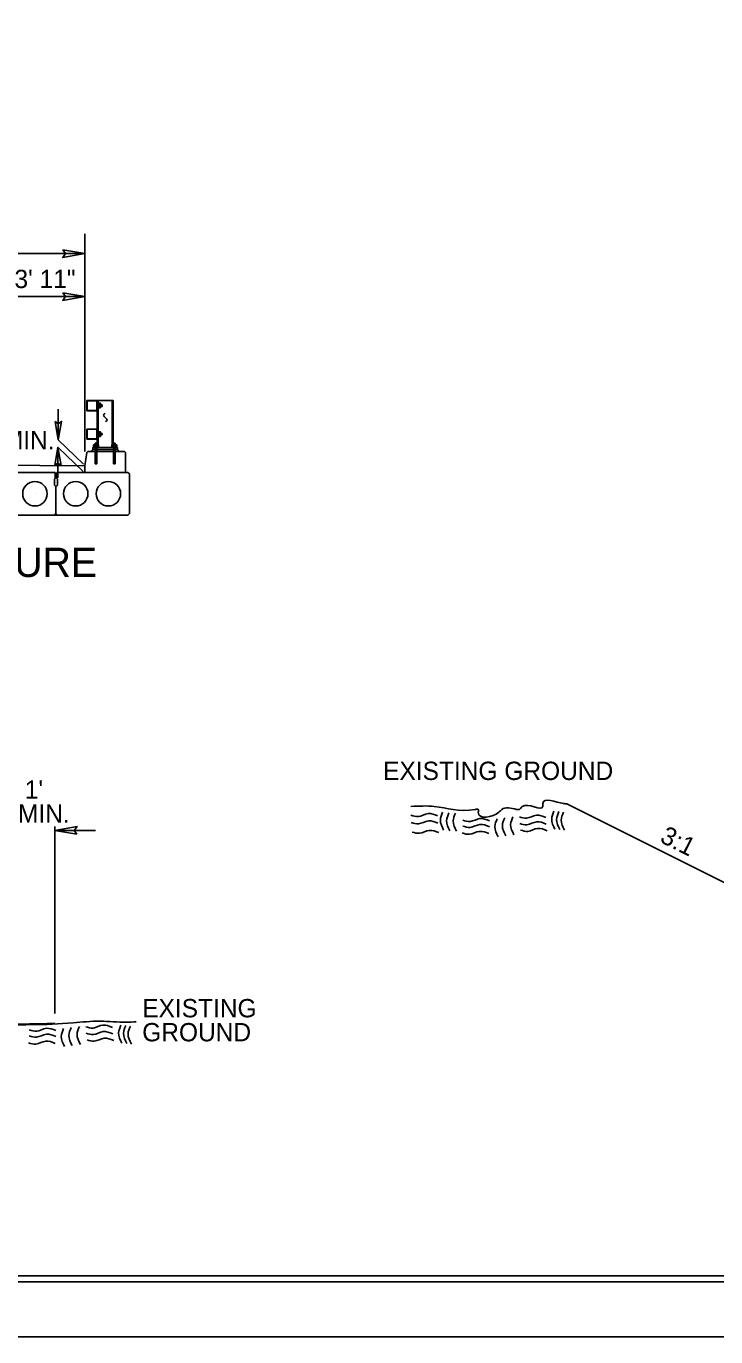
# Model space of a CAD drawing. Extents: x 575722 to 576066, y -53107 to -52774.
# Drawn here: x 575850.6 to 575878.8, y -53106.9 to -53053.2 of the extents above; entities that cross this region are included whole.
import ezdxf

# ---------------------------------------------------------------- set-up
doc = ezdxf.new("R2010")
doc.units = 0
for name, color, linetype in [('Default', 7, 'Continuous'), ('Old_Level_11', 7, 'Continuous'), ('Old_Level_2', 7, 'Continuous'), ('Prop Dimension', 7, 'Continuous'), ('Prop Dimension Text', 7, 'Continuous'), ('Prop DSN Text', 7, 'Continuous'), ('Sheet Cutting Line CELL', 7, 'Continuous'), ('Sheet Plot Border Inside CELL', 7, 'Continuous'), ('Sheet Plot Border Outside CELL', 7, 'Continuous'), ('Sheet Typical CELL', 7, 'Continuous'), ('Typical Slope Point Local CELL', 7, 'Continuous'), ('Typical Terminator CELL', 7, 'Continuous'), ('Typical Text Grade Point CELL', 7, 'Continuous')]:
    doc.layers.add(name, color=color, linetype=linetype)

msp = doc.modelspace()

# ---------------------------------------------------------------- linework, layer by layer
at = {"layer": 'Default'}
for p, q in [((575853.09, -53068.945), (575853.09, -53068.528)), ((575853.09, -53068.528), (575853.507, -53068.528)), ((575853.1, -53068.538), (575853.497, -53068.538)), ((575853.1, -53068.935), (575853.1, -53068.538)), ((575853.497, -53068.935), (575853.497, -53068.538)), ((575853.507, -53070.342), (575853.507, -53068.528)), ((575853.507, -53068.528), (575854.175, -53068.528)), ((575853.507, -53068.945), (575853.507, -53068.528)), ((575853.549, -53070.342), (575853.549, -53068.528)), ((575854.133, -53070.342), (575854.133, -53068.528)), ((575854.175, -53070.342), (575854.175, -53068.528)), ((575853.09, -53068.945), (575853.507, -53068.945)), ((575853.1, -53068.935), (575853.497, -53068.935)), ((575853.549, -53068.643), (575853.655, -53068.643)), ((575853.549, -53068.705), (575853.716, -53068.705)), ((575853.549, -53068.768), (575853.716, -53068.768)), ((575853.549, -53068.831), (575853.655, -53068.831)), ((575853.655, -53068.831), (575853.655, -53068.643)), ((575853.661, -53068.768), (575853.659, -53068.705)), ((575853.671, -53068.768), (575853.669, -53068.705)), ((575853.682, -53068.768), (575853.679, -53068.705)), ((575853.692, -53068.768), (575853.689, -53068.705)), ((575853.702, -53068.768), (575853.699, -53068.705)), ((575853.716, -53068.768), (575853.716, -53068.705)), ((575853.833, -53069.053), (575853.807, -53069.072)), ((575853.803, -53069.189), (575853.894, -53069.276)), ((575853.888, -53069.378), (575853.856, -53069.405)), ((575853.09, -53070.114), (575853.09, -53069.697)), ((575853.09, -53069.697), (575853.507, -53069.697)), ((575853.09, -53070.114), (575853.507, -53070.114)), ((575853.1, -53069.707), (575853.497, -53069.707)), ((575853.1, -53070.103), (575853.1, -53069.707)), ((575853.1, -53070.103), (575853.497, -53070.103)), ((575853.497, -53070.103), (575853.497, -53069.707)), ((575853.507, -53070.114), (575853.507, -53069.697)), ((575853.549, -53069.811), (575853.655, -53069.811)), ((575853.549, -53069.874), (575853.716, -53069.874)), ((575853.549, -53069.937), (575853.716, -53069.937)), ((575853.549, -53069.999), (575853.655, -53069.999)), ((575853.655, -53069.999), (575853.655, -53069.811)), ((575853.661, -53069.937), (575853.659, -53069.874)), ((575853.671, -53069.937), (575853.669, -53069.874)), ((575853.682, -53069.937), (575853.679, -53069.874)), ((575853.692, -53069.937), (575853.689, -53069.874)), ((575853.702, -53069.937), (575853.699, -53069.874)), ((575853.716, -53069.937), (575853.716, -53069.874)), ((575853.007, -53071.199), (575853.084, -53070.656)), ((575853.084, -53070.656), (575853.126, -53070.615)), ((575853.126, -53070.615), (575854.634, -53070.615)), ((575853.257, -53070.615), (575853.34, -53070.531)), ((575853.34, -53070.448), (575854.342, -53070.448)), ((575853.34, -53070.531), (575853.34, -53070.448)), ((575853.34, -53070.531), (575854.342, -53070.531)), ((575853.565, -53070.342), (575853.366, -53070.342)), ((575853.366, -53070.448), (575853.366, -53070.342)), ((575853.429, -53070.448), (575853.429, -53070.281)), ((575853.502, -53070.281), (575853.429, -53070.281)), ((575853.502, -53070.295), (575853.429, -53070.298)), ((575853.502, -53070.305), (575853.429, -53070.308)), ((575853.502, -53070.315), (575853.429, -53070.318)), ((575853.502, -53070.325), (575853.429, -53070.328)), ((575853.502, -53070.336), (575853.429, -53070.339)), ((575853.429, -53071.115), (575853.429, -53070.448)), ((575853.502, -53070.448), (575853.502, -53070.281)), ((575853.502, -53071.115), (575853.502, -53070.448)), ((575853.565, -53070.448), (575853.565, -53070.342)), ((575854.118, -53070.342), (575854.316, -53070.342)), ((575854.118, -53070.448), (575854.118, -53070.342)), ((575854.18, -53070.448), (575854.18, -53070.281)), ((575854.18, -53070.281), (575854.253, -53070.281)), ((575854.18, -53070.295), (575854.253, -53070.298)), ((575854.18, -53070.305), (575854.253, -53070.308)), ((575854.18, -53070.315), (575854.253, -53070.318)), ((575854.18, -53070.325), (575854.253, -53070.328)), ((575854.18, -53070.336), (575854.253, -53070.339)), ((575854.18, -53071.115), (575854.18, -53070.448)), ((575854.253, -53070.448), (575854.253, -53070.281)), ((575854.253, -53071.115), (575854.253, -53070.448)), ((575854.316, -53070.448), (575854.316, -53070.342)), ((575854.342, -53070.531), (575854.342, -53070.448)), ((575854.426, -53070.615), (575854.342, -53070.531)), ((575854.676, -53070.656), (575854.634, -53070.615)), ((575854.676, -53071.47), (575854.676, -53070.656)), ((575853.007, -53071.47), (575853.007, -53071.199)), ((575853.502, -53071.115), (575853.429, -53071.115)), ((575854.18, -53071.115), (575854.253, -53071.115)), ((575848.852, -53071.47), (575851.796, -53071.47)), ((575851.796, -53071.721), (575851.764, -53071.752)), ((575851.764, -53071.992), (575851.764, -53071.752)), ((575851.796, -53071.47), (575851.796, -53071.721)), ((575851.859, -53071.47), (575854.771, -53071.47)), ((575851.859, -53071.721), (575851.859, -53071.47)), ((575851.859, -53071.721), (575851.89, -53071.752)), ((575851.89, -53071.752), (575851.89, -53071.992)), ((575853.007, -53071.47), (575854.676, -53071.47)), ((575854.771, -53071.47), (575854.834, -53071.533)), ((575854.834, -53073.161), (575854.834, -53071.533)), ((575851.827, -53072.055), (575851.764, -53071.992)), ((575851.827, -53072.055), (575851.89, -53071.992)), ((575851.827, -53073.161), (575851.827, -53072.055)), ((575851.827, -53073.161), (575851.827, -53072.055)), ((575850.992, -53072.347), (575850.992, -53072.347)), ((575852.662, -53072.347), (575852.662, -53072.347)), ((575853.999, -53072.347), (575853.999, -53072.347)), ((575854.778, -53073.224), (575821.837, -53073.224)), ((575851.764, -53073.224), (575848.883, -53073.224)), ((575851.827, -53073.161), (575851.764, -53073.224)), ((575851.89, -53073.224), (575851.827, -53073.161)), ((575854.771, -53073.224), (575851.89, -53073.224)), ((575854.834, -53073.161), (575854.771, -53073.224))]:
    msp.add_line(p, q, dxfattribs=at)
msp.add_lwpolyline([(575823.534, -53071.199), (575838.307, -53071.093), (575853.007, -53071.199)], dxfattribs=at)
for centre in [(575850.966, -53072.347), (575852.635, -53072.347), (575853.971, -53072.347)]:
    msp.add_circle(centre, 0.501, dxfattribs=at)
for centre, radius, start, end in [((575853.846, -53069.132), 0.071, 122.9142, 232.7131), ((575853.855, -53069.325), 0.0631, 301.9827, 50.2683)]:
    msp.add_arc(centre, radius, start, end, dxfattribs=at)
at = {"layer": 'Old_Level_11'}
for p, q in [((575853.007, -53070.62), (575853.007, -53061.698)), ((575853.007, -53062.514), (575823.534, -53062.515)), ((575853.007, -53064.271), (575849.407, -53064.271)), ((575852.96, -53071.136), (575851.923, -53070.139)), ((575852.946, -53071.438), (575851.909, -53070.442)), ((575851.784, -53093.624), (575851.784, -53085.977)), ((575853.448, -53086.137), (575851.784, -53086.137))]:
    msp.add_line(p, q, dxfattribs=at)
for points in [[(575852.107, -53062.359), (575853.007, -53062.514), (575852.102, -53062.674), (575852.217, -53062.514)], [(575852.107, -53064.116), (575853.007, -53064.271), (575852.102, -53064.431), (575852.217, -53064.272)], [(575852.684, -53086.292), (575851.784, -53086.137), (575852.689, -53085.977), (575852.574, -53086.137)]]:
    msp.add_lwpolyline(points, close=True, dxfattribs=at)
at = {"layer": 'Old_Level_2'}
for points in [[(575872.735, -53085.046), (575872.592, -53085.03), (575871.752, -53085.03), (575871.752, -53085.15), (575870.912, -53085.15), (575870.792, -53085.27), (575870.672, -53085.27), (575870.072, -53085.27), (575869.952, -53085.39), (575869.112, -53085.39), (575869.112, -53085.27), (575868.992, -53085.27), (575867.312, -53085.15), (575866.356, -53085.15)], [(575867.444, -53085.538), (575867.055, -53085.444), (575866.651, -53085.565), (575866.356, -53085.511)], [(575867.653, -53085.384), (575867.559, -53085.706), (575867.693, -53086.123)], [(575867.908, -53085.41), (575867.814, -53085.733), (575867.949, -53086.15)], [(575868.177, -53085.424), (575868.083, -53085.746), (575868.217, -53086.163)], [(575869.568, -53085.74), (575869.178, -53085.646), (575868.775, -53085.767), (575868.479, -53085.713)], [(575869.884, -53085.652), (575869.79, -53085.975), (575869.924, -53086.392)], [(575870.193, -53085.612), (575870.099, -53085.935), (575870.233, -53086.351)], [(575870.529, -53085.572), (575870.435, -53085.894), (575870.569, -53086.311)], [(575871.88, -53085.605), (575871.49, -53085.511), (575871.087, -53085.632), (575870.791, -53085.578)], [(575872.209, -53085.343), (575872.115, -53085.666), (575872.249, -53086.083)], [(575872.411, -53085.357), (575872.317, -53085.679), (575872.451, -53086.096)], [(575872.599, -53085.384), (575872.505, -53085.706), (575872.639, -53086.123)], [(575867.458, -53085.834), (575867.068, -53085.74), (575866.665, -53085.861), (575866.369, -53085.807)], [(575867.498, -53086.224), (575867.108, -53086.13), (575866.705, -53086.251), (575866.409, -53086.197)], [(575869.541, -53086.264), (575869.151, -53086.17), (575868.748, -53086.291), (575868.452, -53086.237)], [(575869.568, -53085.982), (575869.178, -53085.888), (575868.775, -53086.009), (575868.479, -53085.955)], [(575871.893, -53085.874), (575871.503, -53085.78), (575871.1, -53085.901), (575870.805, -53085.847)], [(575871.934, -53086.143), (575871.544, -53086.049), (575871.141, -53086.17), (575870.845, -53086.116)], [(575855.112, -53093.968), (575854.703, -53093.989), (575853.632, -53093.941), (575852.526, -53094.014), (575849.124, -53094.098), (575844.384, -53094.267), (575839.88, -53094.132), (575832.25, -53093.93), (575830.77, -53093.928), (575830.012, -53093.961), (575829.277, -53094.016), (575829.167, -53094.013), (575829.057, -53093.998), (575828.948, -53093.984), (575828.838, -53093.983), (575828.716, -53094.002), (575828.596, -53094.03), (575828.476, -53094.06), (575828.355, -53094.082), (575827.8, -53094.137), (575827.68, -53094.137), (575827.26, -53094.109), (575826.84, -53094.068), (575826, -53094.017), (575825.044, -53094.017), (575823.437, -53093.971), (575821.903, -53094.025)], [(575851.824, -53094.33), (575851.435, -53094.236), (575851.031, -53094.357), (575850.736, -53094.303)], [(575852.14, -53094.243), (575852.046, -53094.565), (575852.181, -53094.982)], [(575852.449, -53094.203), (575852.355, -53094.525), (575852.49, -53094.942)], [(575852.785, -53094.162), (575852.691, -53094.485), (575852.826, -53094.902)], [(575854.136, -53094.196), (575853.746, -53094.102), (575853.343, -53094.223), (575853.048, -53094.169)], [(575854.484, -53094.103), (575854.39, -53094.425), (575854.524, -53094.842)], [(575854.685, -53094.116), (575854.591, -53094.439), (575854.726, -53094.855)], [(575854.873, -53094.143), (575854.779, -53094.466), (575854.914, -53094.882)], [(575851.797, -53094.855), (575851.408, -53094.76), (575851.005, -53094.881), (575850.709, -53094.828)], [(575851.824, -53094.572), (575851.435, -53094.478), (575851.031, -53094.599), (575850.736, -53094.545)], [(575854.15, -53094.465), (575853.76, -53094.371), (575853.357, -53094.492), (575853.061, -53094.438)], [(575854.19, -53094.734), (575853.8, -53094.639), (575853.397, -53094.76), (575853.101, -53094.707)]]:
    msp.add_spline(points, degree=3, dxfattribs=at)
at = {"layer": 'Prop Dimension'}
for p, q in [((575851.923, -53068.889), (575851.923, -53070.139)), ((575851.909, -53070.442), (575851.909, -53071.692))]:
    msp.add_line(p, q, dxfattribs=at)
at = {"layer": 'Prop DSN Text'}
msp.add_open_spline([(575851.784, -53094.032), (575850.897, -53094.054), (575850.01, -53094.076), (575849.124, -53094.098), (575848.729, -53094.108), (575848.334, -53094.127), (575847.939, -53094.144), (575847.544, -53094.161), (575847.149, -53094.187), (575846.754, -53094.205), (575845.964, -53094.242), (575845.174, -53094.279), (575844.384, -53094.267), (575843.634, -53094.255), (575842.883, -53094.231), (575842.132, -53094.207), (575841.381, -53094.182), (575840.631, -53094.153), (575839.88, -53094.132), (575838.609, -53094.096), (575837.337, -53094.063), (575836.065, -53094.029), (575834.793, -53093.994), (575833.522, -53093.962), (575832.25, -53093.93), (575831.757, -53093.918), (575831.263, -53093.919), (575830.77, -53093.928), (575830.517, -53093.933), (575830.265, -53093.948), (575830.012, -53093.961), (575829.767, -53093.974), (575829.522, -53094.004), (575829.277, -53094.016), (575829.24, -53094.018), (575829.204, -53094.017), (575829.167, -53094.013), (575829.131, -53094.008), (575829.094, -53094.003), (575829.057, -53093.998), (575829.021, -53093.993), (575828.984, -53093.988), (575828.948, -53093.984), (575828.911, -53093.98), (575828.874, -53093.98), (575828.838, -53093.983), (575828.797, -53093.987), (575828.756, -53093.993), (575828.716, -53094.002), (575828.676, -53094.011), (575828.636, -53094.021), (575828.596, -53094.03), (575828.556, -53094.04), (575828.516, -53094.05), (575828.476, -53094.06), (575828.436, -53094.069), (575828.396, -53094.076), (575828.355, -53094.082), (575828.171, -53094.11), (575827.986, -53094.129), (575827.8, -53094.137), (575827.76, -53094.139), (575827.72, -53094.139), (575827.68, -53094.137), (575827.54, -53094.13), (575827.4, -53094.121), (575827.26, -53094.109), (575827.12, -53094.096), (575826.981, -53094.08), (575826.84, -53094.068), (575826.561, -53094.045), (575826.281, -53094.017), (575826, -53094.017), (575825.681, -53094.017), (575825.362, -53094.017), (575825.044, -53094.017)], degree=3, dxfattribs=at)
at = {"layer": 'Sheet Cutting Line CELL'}
msp.add_line((575797.38, -53106.867), (575965.78, -53106.867), dxfattribs=at)
at = {"layer": 'Sheet Plot Border Inside CELL'}
msp.add_lwpolyline([(575965.33, -52999.112), (575798.68, -52999.112), (575798.68, -53104.622), (575965.33, -53104.622)], close=True, dxfattribs=at)
at = {"layer": 'Sheet Plot Border Outside CELL'}
msp.add_lwpolyline([(575965.78, -52996.867), (575797.38, -52996.867), (575797.38, -53106.867), (575965.78, -53106.867)], close=True, dxfattribs=at)
at = {"layer": 'Sheet Typical CELL'}
msp.add_lwpolyline([(575964.08, -52999.367), (575814.08, -52999.367), (575814.08, -53104.367), (575964.08, -53104.367)], close=True, dxfattribs=at)
at = {"layer": 'Typical Slope Point Local CELL'}
msp.add_line((575872.735, -53085.046), (575880.664, -53089.01), dxfattribs=at)
at = {"layer": 'Typical Terminator CELL'}
for points in [[(575851.794, -53069.39), (575851.923, -53070.139), (575852.056, -53069.385), (575851.923, -53069.481)], [(575852.038, -53071.192), (575851.909, -53070.442), (575851.776, -53071.196), (575851.909, -53071.1)]]:
    msp.add_lwpolyline(points, close=True, dxfattribs=at)

# ---------------------------------------------------------------- texts
at = {"layer": 'Old_Level_11'}
for s, p in [('3\' 11"', (575850.129, -53063.926)), ('MIN.', (575849.654, -53070.53)), (" 1'", (575850.273, -53084.833)), ('MIN.', (575850.273, -53085.816))]:
    msp.add_text(s, height=0.75, rotation=360, dxfattribs=at).set_placement(p)
at = {"layer": 'Prop Dimension Text'}
msp.add_text('TYPICAL SECTION ON STRUCTURE', height=1.2, dxfattribs=at).set_placement((575826.049, -53075.756))
at = {"layer": 'Typical Slope Point Local CELL'}
msp.add_text('3:1', height=0.75, rotation=333.435, dxfattribs=at).set_placement((575876.503, -53086.588))
at = {"layer": 'Typical Text Grade Point CELL'}
for s, p in [('EXISTING GROUND', (575865.216, -53084.067)), ('EXISTING', (575855.357, -53093.786)), ('GROUND', (575855.357, -53094.769))]:
    msp.add_text(s, height=0.75, dxfattribs=at).set_placement(p)

doc.saveas('drawing.dxf')
